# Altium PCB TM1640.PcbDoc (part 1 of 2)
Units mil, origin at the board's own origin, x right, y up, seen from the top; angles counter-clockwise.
Board outline 3858.42 x 1968.54 mil, 2 copper layers (Top Layer, Bottom Layer); 104 components, 33 nets, 245 pads, 113 vias.
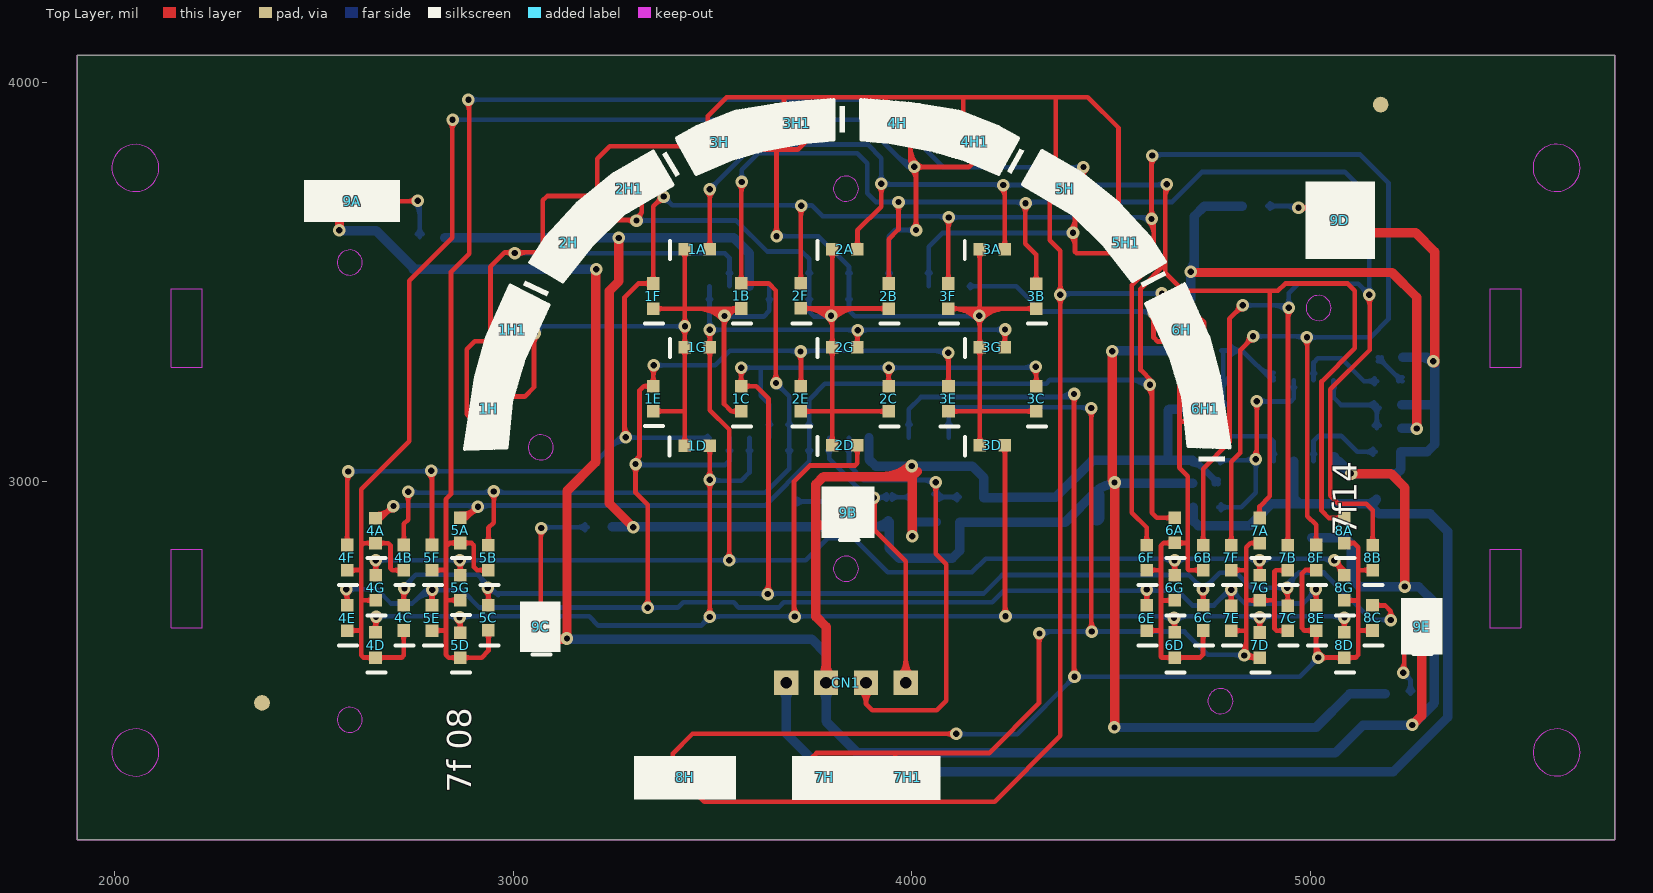
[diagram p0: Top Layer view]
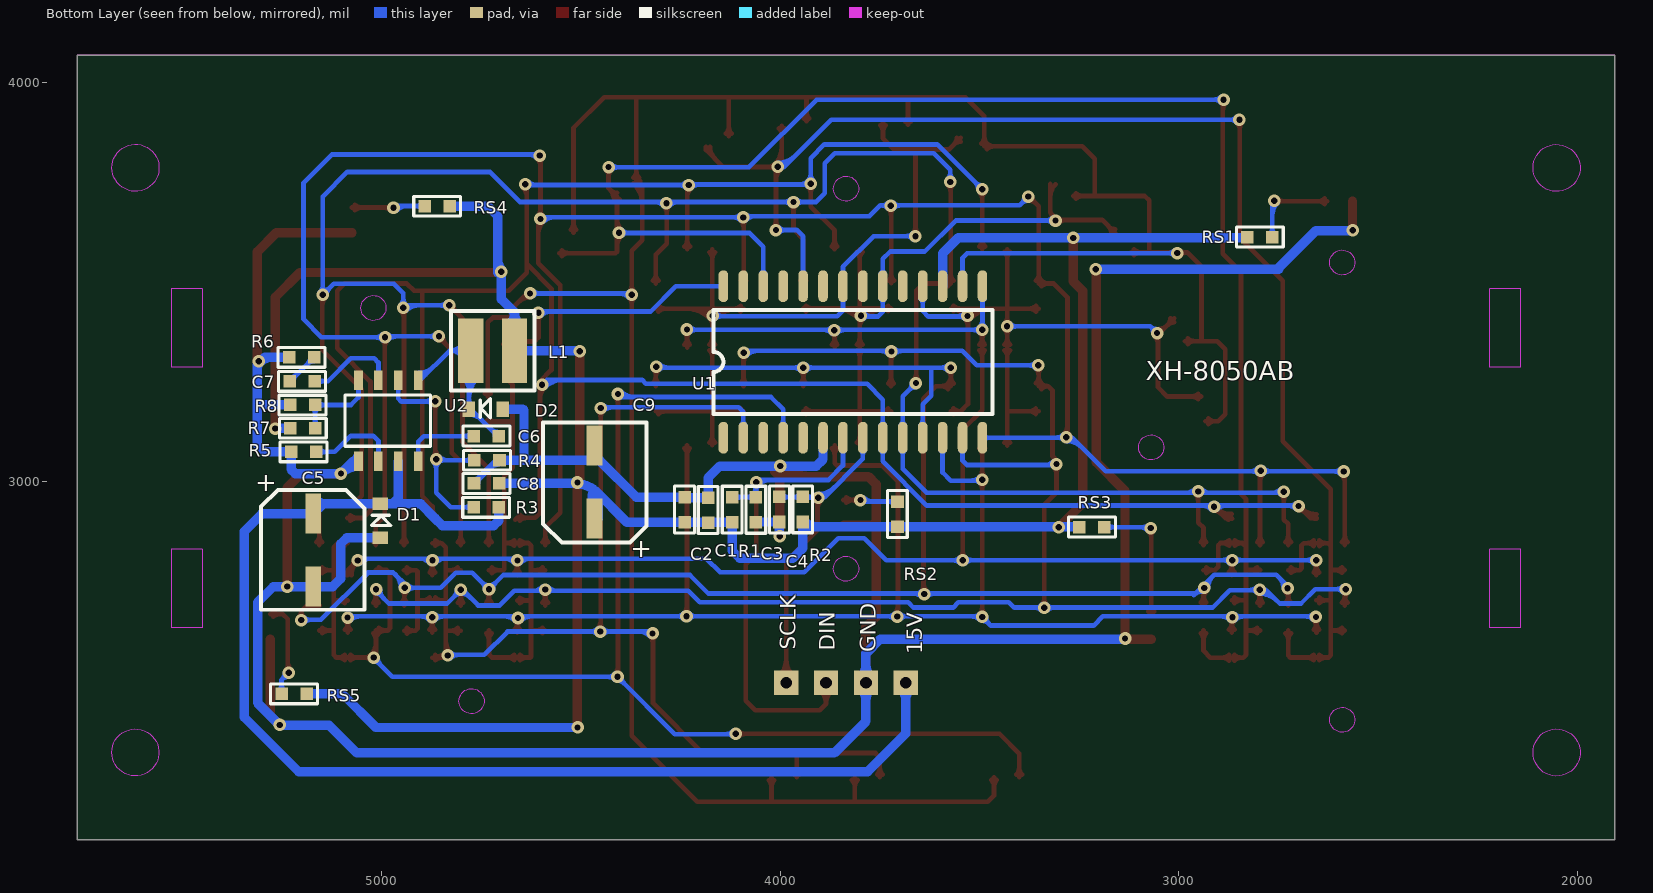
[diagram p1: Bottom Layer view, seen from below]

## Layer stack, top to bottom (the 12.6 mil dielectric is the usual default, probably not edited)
Top Solder: solder mask 0.4, Solder Resist, Dk 3.5
Top Layer: signal copper 1.4
Dielectric 1: dielectric 12.6, FR-4, Dk 4.8
Bottom Layer: signal copper 1.4
Bottom Solder: solder mask 0.4, Solder Resist, Dk 3.5

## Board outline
1905.23,2101.17 5763.65,2101.17 5763.65,4069.72 1905.23,4069.72

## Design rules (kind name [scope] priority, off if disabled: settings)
Clearance [All] p1: gap=10 ignorepadtopadclearanceinfootprint=FALSE
PlaneClearance [All] p1: clearance=0
PolygonConnect [All] p1: connectstyle=Relief reliefconductorwidth=10 reliefentries=4 polygonreliefangle="90 Angle" airgapwidth=10
RoutingPriority [All] p1: routingpriority=4
RoutingVias [All] p1: holewidth=20 width=50 viastyle="Through Hole" minholewidth=28 minwidth=50 maxholewidth=28 maxwidth=50
SolderMaskExpansion [All] p1: expansion=4
Width [All] p1: maxlimit=39.37 minlimit=39.37 preferedwidth=10
28 further rules are at their usual default settings.

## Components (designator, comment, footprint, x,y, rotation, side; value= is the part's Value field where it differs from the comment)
1A "Diode" 0603 3461.42,3582.44 r0 top
1B "Diode" 0603 3571.69,3465.28 r90 top
1C "Diode" 0603 3571.46,3207.4 r90 top
1D "Diode" 0603 3461.26,3090 r0 top
1E "Diode" 0603 3351.06,3207.52 r90 top
1F "Diode" 0603 3350.91,3465 r90 top
1G "Diode" 0603 3461.46,3336.22 r0 top
1H "Diode" 0603 2938.11,3181.93 r260 top
1H1 "Diode" 0603 2997.36,3380.47 r245 top
2A "Diode" 0603 3831.65,3582.44 r0 top
2B "Diode" 0603 3941.81,3465 r90 top
2C "Diode" 0603 3941.53,3207.28 r90 top
2D "Diode" 0603 3831.5,3090.43 r0 top
2E "Diode" 0603 3721.42,3207.24 r90 top
2F "Diode" 0603 3721.14,3465.39 r90 top
2G "Diode" 0603 3831.5,3336.22 r0 top
2H "Diode" 0603 3138.94,3598.9 r230 top
2H1 "Diode" 0603 3290.2,3734.13 r215 top
3A "Diode" 0603 4201.42,3582.2 r0 top
3B "Diode" 0603 4311.73,3464.96 r90 top
3C "Diode" 0603 4311.85,3207.4 r90 top
3D "Diode" 0603 4201.61,3090.28 r0 top
3E "Diode" 0603 4091.53,3207.24 r90 top
3F "Diode" 0603 4091.3,3465 r90 top
3G "Diode" 0603 4201.57,3336.22 r0 top
3H "Diode" 0603 3517.09,3851.53 r200 top
3H1 "Diode" 0603 3710.32,3898.07 r185 top
4A "Diode" 0603 2654.05,2876.61 r90 top
4B "Diode" 0603 2725.04,2808.98 r90 top
4C "Diode" 0603 2724.68,2657.4 r90 top
4D "Diode" 0603 2654.05,2589.53 r90 top
4E "Diode" 0603 2582.95,2657.32 r90 top
4F "Diode" 0603 2583.03,2809.01 r90 top
4G "Diode" 0603 2654.29,2733.11 r90 top
4H "Diode" 0603 3964.72,3898.07 r170 top
4H1 "Diode" 0603 4156.89,3852.44 r155 top
5A "Diode" 0603 2866.3,2876.93 r90 top
5B "Diode" 0603 2937.44,2808.78 r90 top
5C "Diode" 0603 2937.44,2657.56 r90 top
5D "Diode" 0603 2866.77,2589.33 r90 top
5E "Diode" 0603 2795.71,2657.32 r90 top
5F "Diode" 0603 2795.83,2809.01 r90 top
5G "Diode" 0603 2866.46,2733.5 r90 top
5H "Diode" 0603 4384.69,3734.49 r140 top
5H1 "Diode" 0603 4536.14,3598.39 r125 top
6A "Diode" 0603 4659.65,2877.13 r90 top
6B "Diode" 0603 4730.43,2808.74 r90 top
6C "Diode" 0603 4730.35,2657.4 r90 top
6D "Diode" 0603 4659.45,2589.53 r90 top
6E "Diode" 0603 4588.74,2657.32 r90 top
6F "Diode" 0603 4588.66,2808.7 r90 top
6G "Diode" 0603 4659.57,2732.91 r90 top
6H "Diode" 0603 4676.81,3380.47 r110 top
6H1 "Diode" 0603 4735.71,3181.93 r95 top
7A "Diode" 0603 4872.01,2876.73 r90 top
7B "Diode" 0603 4943.11,2808.66 r90 top
7C "Diode" 0603 4942.8,2657.09 r90 top
7D "Diode" 0603 4872.24,2589.45 r90 top
7E "Diode" 0603 4801.34,2657.13 r90 top
7F "Diode" 0603 4801.34,2808.82 r90 top
7G "Diode" 0603 4872.13,2733.11 r90 top
7H "Diode" 0603 3780.91,2257.6 r0 top
7H1 "Diode" 0603 3989.76,2257.52 r0 top
8A "Diode" 0603 5084.96,2876.73 r90 top
8B "Diode" 0603 5155.71,2808.78 r90 top
8C "Diode" 0603 5155.39,2657.4 r90 top
8D "Diode" 0603 5084.69,2589.53 r90 top
8E "Diode" 0603 5013.78,2657.32 r90 top
8F "Diode" 0603 5013.9,2809.01 r90 top
8G "Diode" 0603 5084.69,2732.91 r90 top
8H "Diode" 0603 3431.46,2257.6 r0 top
9A "Diode" 0603 2595.2,3702.91 r0 top
9B "Diode" 0603 3840.59,2921.73 r90 top
9C "Diode" 0603 3068.58,2635.24 r90 top
9D "Diode" 0603 5073.74,3655.63 r90 top
9E "Diode" 0603 5278.46,2635.67 r90 top
C1 "Cap" 电阻正面 4179.92,2927.76 r270 bottom
C2 "Cap" 电阻正面 4239.21,2929.21 r270 bottom
C3 "Cap" 电阻正面 4060.94,2929.21 r90 bottom
C4 "Cap" 电阻正面 4001.65,2929.68 r90 bottom
C5 "Cap Pol2" 电解电容47UF 5171.02,2918.94 r180 bottom
C6 "Cap" 电阻正面 4736.93,3113.62 r0 bottom
C7 "Cap" 电阻正面 5198.9,3251.5 r180 bottom
C8 "Cap" 电阻正面 4736.26,2994.96 r180 bottom
C9 "Cap Pol2" 电解电容47UF 4465.55,2906.5 r0 bottom
CN1 "Header 4" 0.75(1-4) 3684.44,2494.68 r0 top
D1 "TVS" SOD-323 5002.8,2858.86 r90 top
D2 "TVS" SOD-323 4696.06,3181.38 r0 top
L1 "Inductor" 电感404018 4775.98,3328.23 r90 bottom
R1 "Res2" 电阻正面 4119.72,2928.74 r270 bottom
R2 "Res2" 电阻正面 3942.87,2929.68 r270 bottom
R3 "Res2" 电阻正面 4736.73,2935.24 r180 bottom
R4 "Res2" 电阻正面 4735.24,3052.76 r0 bottom
R5 "Res2" 电阻正面 5195.04,3074.29 r180 bottom
R6 "Res2" 电阻正面 5200.2,3311.57 r180 bottom
R7 "Res2" 电阻正面 5197.6,3133.07 r0 bottom
R8 "Res2" 电阻正面 5197.6,3191.85 r180 bottom
RS1 "Res2" 电阻正面 2796.5,3612.99 r0 bottom
RS2 "Res2" 电阻正面 3705.24,2917.91 r270 bottom
RS3 "Res2" 电阻正面 3217.83,2885.28 r0 bottom
RS4 "Res2" 电阻正面 4859.76,3690.79 r180 bottom
RS5 "Res2" 电阻正面 5219.06,2467.4 r180 bottom
U1 "Component_1" sop28 4142.13,3109.68 r90 bottom locked
U2 "MP1584" SOP8 4907.52,3253.66 r0 top locked

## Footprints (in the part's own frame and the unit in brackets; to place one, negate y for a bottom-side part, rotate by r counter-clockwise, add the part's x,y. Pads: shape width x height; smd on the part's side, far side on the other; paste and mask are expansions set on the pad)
0.75(1-4) [mm]
  rect 1.54x1.54 hole 0.75: 1(0,0) 2(2.54,0) 3(5.08,0) 4(7.62,0)
0603 [mm]
  rect 0.8x0.8 smd: 1(0.8,0) 2(-0.8,0)
  silkscreen extent -1.75,-0.63 -1.75,0.52
SOD-323 [mm]
  rect 0.8x1 smd far side: 1(0,0) 2(2.15,0)
SOP8 [mm]
  rect 0.55x1.25 smd far side: 1(0,0) 2(1.27,0) 3(2.54,0) 4(3.81,0) 5(3.81,-5.15) 6(2.54,-5.15) 7(1.27,-5.15) 8(0,-5.15)
  round 0.8 on Bottom Overlay: 9(-0.038,-1.664)
sop28 [mil]
  oval 80x24 smd: 1(0,0) 2(0,-50) 3(0,-100) 4(0,-150) 5(0,-200) 6(0,-250) 7(0,-300) 8(0,-350) 9(0,-400) 10(0,-450) 11(0,-500) 12(0,-550) 13(0,-600) 14(0,-650) 15(380,-650) 16(380,-600) 17(380,-550) 18(380,-500) 19(380,-450) 20(380,-400) 21(380,-350) 22(380,-300) 23(380,-250) 24(380,-200) 25(380,-150) 26(380,-100) 27(380,-50) 28(380,0)
  silkscreen extent 60,-675 320,25
电感404018 [mm]
  rect 4.1x1.6 smd: 1(0,0) 2(0,-2.8)
  silkscreen extent -2.55,-4.08 2.53,1.26
电解电容47UF [mm]
  rect 1x2.55 smd: 1(0,0) 2(0,-4.65)
  silkscreen extent -3.32,-6.12 3.27,1.52
电阻正面 [mm]
  rect 0.8x0.8 smd: 1(-0.8,0) 2(0.8,0)
  silkscreen extent -1.5,-0.64 1.49,0.62

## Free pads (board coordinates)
  round 39.37 smd: 1(2369.25,2444.29) 2(5175.79,3945.47)

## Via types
v1: diameter 31.5, hole 15.75, Top Layer to Bottom Layer, 113 vias

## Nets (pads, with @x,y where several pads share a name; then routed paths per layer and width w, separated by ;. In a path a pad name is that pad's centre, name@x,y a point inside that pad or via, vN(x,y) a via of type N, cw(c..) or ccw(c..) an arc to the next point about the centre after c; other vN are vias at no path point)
5V: C1.2 C2.2 C8.2 C9.1 L1.2 R1.2 R2.2 R7.2 RS1.2 RS2.2 RS3.2 RS4.2 RS5.2 U1.17 | length 6721.8
  Top Layer w23.62: v1(3264.61,3610.91) 3264.61,3501.97 3240.39,3477.76 3240.39,2945.43 v1(3300.71,2885.12) ; v1@4502.2,3002.76 v1(4502.2,3326.85) ; v1@4508.23,2384.17 v1(4508.23,2997.24) ; v1@4700.43,3524.17 5204.25,3524.17 5266.42,3462.01 v1(5266.42,3132.56)
  Bottom Layer w23.62: RS1.2@2827.48,3610.91 v1(3264.61,3610.91) 3553.19,3610.91 3592.13,3571.97 U1.17@3592.13,3489.68 ; RS3.2@3248.15,2886.42 RS2.2@3705.24,2886.42 R2.2@3938.11,2886.42 ; 3904.95,2886.42 ccw(c3904.95,2936.11) R2.2@3940.09,2900.97 ; R2.2@3942.87,2898.19 3942.87,2831.89 3967.64,2807.13 4100.98,2807.13 4119.72,2825.87 R1.2@4119.72,2897.24 4383.86,2897.24 4463.58,2976.97 ; 4463.58,2976.71 cw(c4508.23,2924.97) v1@4508.23,2993.31 ; v1@4505.12,3328.23 L1.2@4665.75,3328.23 4665.75,3423.98 4699.13,3457.36 v1(4699.13,3525.98) ; v1(4507.87,2382.72) 5013.82,2382.72 5098.5,2467.4 RS5.2@5187.56,2467.4 ; v1@4508.23,2994.96 C8.2@4704.76,2994.96 ; L1.2@4652.04,3391.57 ccw(c4620.59,3423.97) 4665.75,3423.97 ccw(c4710.9,3423.97) L1.2@4679.46,3391.57 ; v1@4696.35,3528.77 ccw(c4668.34,3556.78) 4707.95,3556.78 ; v1@4707.95,3523.58 4707.95,3665.16 4733.58,3690.79 RS4.2@4828.27,3690.79 ; R7.2@5229.09,3133.07 v1@5266.06,3133.07
  Bottom Layer w39.37: C9.1@4463.58,2908.46 4463.58,2964.57
15V: C5.1 CN1.1 D1.2 R3.2 U2.7 | length 3313.9
  Bottom Layer w23.62: CN1.1@3671.35,2481.59 cw(c3639.77,2450.01) 3684.44,2450.01 cw(c3729.11,2450.01) CN1.1@3697.52,2481.59 ; CN1.1@3684.44,2494.68 3684.44,2367.65 3780.28,2271.81 5207.64,2271.81 5344.37,2408.54 5344.37,2874.41 5299.84,2918.94 C5.1@5171.02,2918.94 5146.46,2943.5 ; R3.2@4705.24,2935.24 4705.24,2902.01 4717.99,2889.25 4847.28,2889.25 4865.35,2907.32 4901.53,2943.5 4972.48,2943.5 ; U2.7@4957.52,3050.91 4957.52,2958.46 4972.48,2943.5 ; 5137.66,2943.5 ccw(c5137.66,2982.81) C5.1@5165.46,2955.02 ; C5.1@5164.29,2953.54 cw(c5146.46,2964.38) 5146.46,2943.5 ; 4972.48,2943.5 D1.2@5002.8,2943.5 5146.46,2943.5
DIN: C3.2 CN1.3 R1.1 U1.7 | length 1545.6
  Top Layer w11.81: CN1.3@3868.75,2475.98 cw(c3840.52,2442.33) 3884.44,2442.33 ; CN1.3@3884.44,2494.68 3884.44,2442.33 ; CN1.3@3900.13,2475.98 ccw(c3928.36,2442.33) 3884.44,2442.33 ; v1@4052.57,2991.27 cw(c4035.76,2974.47) 4059.53,2974.47 cw(c4083.29,2974.47) v1@4066.49,2991.27 ; v1(4059.53,2998.23) 4059.53,2818.78 4086.26,2792.05 4086.26,2449.84 4062.36,2425.94 3900.83,2425.94 3884.44,2442.33
  Bottom Layer w11.81: U1.7@3837.82,3077.37 cw(c3827.41,3066.97) 3842.12,3066.97 ; 3842.13,3066.97 cw(c3856.84,3066.97) U1.7@3846.44,3077.37 ; U1.7@3842.13,3109.68 3842.13,3040 3878.35,3003.78 4026.99,3003.78 ; v1@4051.92,2991.99 ccw(c4027,2971.55) 4027,3003.78 ; v1@4052.57,2991.27 cw(c4032.34,2971.04) C3.2@4060.94,2971.04 ; C3.2@4053.98,2967.67 ccw(c4037.18,2984.47) 4060.94,2984.47 ccw(c4084.71,2984.47) 4067.9,2967.67 ccw(c4084.71,2984.47) 4084.71,2960.71 ccw(c4084.71,2936.95) C3.2@4067.9,2953.75 ; 4060.95,2977.89 cw(c4079.87,2977.89) v1@4066.49,2991.27 ; 4094.82,2960.71 cw(c4094.82,2935.33) R1.1@4112.76,2953.28 ; 4097.1,2960.71 ccw(c4097.1,2982.86) R1.1@4112.76,2967.2 ; R1.1@4119.25,2960.71 C3.2@4060.94,2960.71 4060.94,2996.1 4053.27,3003.78 4026.99,3003.78
GND: 9A.2 9B.2 9C.2 9D.2 9E.2 C1.1 C2.1 C3.1 C4.1 C5.2 C8.1 C9.2 CN1.2 D1.1 D2.1 R4.1 R5.1 R6.1 R8.1 U1.6 U2.5 | length 9586.3
  Top Layer w23.62: v1@2563.7,3630.98 9A.2@2563.7,3702.91 ; 9C.2@3068.58,2603.74 v1@3132.16,2603.74 ; v1(3134.37,2605.94) 3134.37,2976.1 3206.77,3048.5 v1@3206.77,3532.32 ; CN1.2@3771.35,2507.76 ccw(c3739.77,2539.35) 3784.44,2539.35 ccw(c3829.11,2539.35) CN1.2@3797.52,2507.76 ; CN1.2@3784.44,2494.68 3784.44,2635.24 3758.94,2660.75 3758.94,2898.23 ; 9B.2@3840.59,2890.24 3766.93,2890.24 3758.94,2898.23 ; 3925.51,3011.97 ccw(c3925.51,3112.88) v1@3996.86,3041.52 ; 3982.54,3011.97 ccw(c3982.54,3055.85) 4013.56,3024.82 ; 3999.13,3011.97 3778.11,3011.97 3758.94,2992.8 3758.94,2898.23 ; v1(4000.35,2862.76) v1@4000.35,3032.44 ; 9D.2@5073.74,3624.13 5263.27,3624.13 5311.65,3575.75 v1@5311.65,3297.4 ; v1@5106.22,3019.49 5201.57,3019.49 5236.46,2984.61 v1(5236.46,2736.26) ; v1(5255.35,2388.98) 5278.46,2412.09 9E.2@5278.46,2604.17 ; v1@5305.13,3304.08 ccw(c5289.38,3319.83) 5311.65,3319.83
  Bottom Layer w15.75: R4.1@4703.74,3044.88 cw(c4703.74,3010.86) 4727.8,3034.92 ; R4.1@4709.96,3052.76 C8.1@4767.76,2994.96 ; C8.1@4759.88,2994.96 ccw(c4740.88,2994.96) 4754.31,3008.4 ccw(c4767.76,3021.85) C8.1@4767.76,3002.83
  Bottom Layer w23.62: v1@2563.7,3629.17 2655.2,3629.17 2747.95,3536.42 ; 2748.39,3532.64 v1@3208.74,3532.64 ; v1@3136.26,2604.49 3748.43,2604.49 3784.44,2568.47 CN1.2@3784.44,2494.68 3784.44,2397.88 3863.54,2318.78 5061.81,2318.78 5131.42,2388.39 v1@5254.49,2388.39 ; CN1.2@3771.35,2481.59 cw(c3739.77,2450.01) 3784.44,2450.01 cw(c3829.11,2450.01) CN1.2@3797.52,2481.59 ; CN1.2@3771.35,2507.76 ccw(c3739.77,2539.35) 3784.44,2539.35 ccw(c3829.11,2539.35) CN1.2@3797.52,2507.76 ; U1.6@3892.13,3109.68 3892.13,3055.16 3909.33,3037.95 4151.46,3037.95 4179.92,3009.49 C1.1@4179.92,2959.25 C2.1@4237.76,2959.25 ; v1@4001.65,2862.76 C4.1@4001.65,2898.19 C3.1@4060.47,2898.19 ; C2.1@4239.21,2960.71 4360.51,2960.71 4452.56,3052.76 4649.69,3052.76 ; D2.1@4696.06,3181.38 4645.16,3181.38 4642.2,3178.43 4642.2,3060.24 4649.69,3052.76 ; R4.1@4703.74,3052.76 4649.69,3052.76 ; D1.1@5002.8,2858.86 5086.53,2858.86 5101.97,2843.43 5101.97,2756.26 5122.36,2735.87 C5.2@5171.02,2735.87 5271.53,2735.87 5310.75,2696.65 5310.75,2444.37 v1(5255.35,2388.98) ; U2.5@5057.52,3038.11 cw(c5057.52,2976.33) v1@5101.2,3020.01 ; U2.5@5057.52,3050.91 5070.31,3050.91 v1(5101.5,3019.72) 5216.1,3019.72 5226.53,3030.16 R5.1@5226.53,3074.29 5292.6,3074.29 5311.65,3093.35 5311.65,3293.11 5293.19,3311.57 R6.1@5231.69,3311.57 ; U2.5@5057.52,3061.73 cw(c5057.52,3056.98) U2.5@5060.88,3060.34 ; R8.1@5229.09,3191.85 5307.16,3191.85 ; 5273.6,3311.57 cw(c5273.6,3266.99) 5305.13,3298.51 cw(c5289.38,3282.76) 5311.65,3282.76
  other v1: 3999.64,3038.74 5307.91,3301.3 3208.15,3532.32 2563.03,3630.31
GRID1: 1A.2 1B.2 1C.2 1D.2 1E.2 1F.2 1G.2 1H1.2 1H.2 U1.18 | length 2898.4
  Top Layer w11.81: 1H.2@2943.58,3212.95 3028.54,3212.95 3051.69,3236.1 3051.69,3368 1H1.2@3010.67,3409.02 ; 1H.2@2950.54,3205.99 cw(c2967.34,3189.18) 2967.34,3212.95 cw(c2967.34,3236.71) 1H.2@2950.54,3219.91 ; 1H1.2@3010.67,3399.17 cw(c3010.67,3375.41) 3027.47,3392.21 ; 1H1.2@3020.52,3409.02 ccw(c3044.28,3409.02) 3027.48,3392.22 ; 3026.2,3393.49 ccw(c3054.01,3421.3) v1@3054.01,3381.97 ; v1@3047.06,3365.17 cw(c3035.86,3353.97) 3051.69,3353.97 ; 3051.69,3342.76 cw(c3083.39,3342.76) v1@3060.98,3365.17 ; 1F.2@3350.91,3433.5 3429.92,3433.5 ; 1E.2@3351.06,3176.02 3427.52,3176.02 ; 1F.2@3357.87,3426.54 cw(c3374.67,3409.74) 3374.67,3433.5 cw(c3374.67,3457.26) 1F.2@3357.87,3440.46 ; 1E.2@3358.02,3169.06 cw(c3374.82,3152.26) 3374.82,3176.02 cw(c3374.82,3199.78) 1E.2@3358.02,3182.98 ; 1D.2@3422.8,3096.96 ccw(c3405.62,3114.14) 3429.92,3114.14 ; 1A.2@3422.96,3575.48 cw(c3406.16,3558.68) 3429.92,3558.68 cw(c3453.68,3558.68) 1A.2@3436.88,3575.48 ; 1G.2@3423,3329.26 cw(c3406.29,3312.55) 3429.92,3312.55 ; 1G.2@3423,3343.18 ccw(c3406.29,3359.89) 3429.92,3359.89 ; v1@3423.28,3382.06 cw(c3407.23,3366.01) 3429.92,3366.01 ; v1@3423.28,3395.98 ccw(c3407.23,3412.02) 3429.92,3412.02 ; 1D.2@3429.92,3090.16 3429.92,3389.01 3429.92,3433.5 ; 3429.92,3113.38 ccw(c3453.14,3113.38) 1D.2@3436.72,3096.96 ; 3429.92,3312.36 cw(c3453.82,3312.36) 1G.2@3436.92,3329.26 ; 3429.92,3360.08 ccw(c3453.82,3360.08) 1G.2@3436.92,3343.18 ; 3429.92,3364.49 cw(c3454.76,3364.49) v1@3437.2,3382.06 ; 3429.92,3413.54 ccw(c3454.76,3413.54) v1@3437.2,3395.98 ; 1A.2@3429.92,3582.44 3429.92,3433.5 ; 3461.5,3433.5 cw(c3461.5,3346.97) 3522.69,3408.16 cw(c3508.73,3394.2) 3528.47,3394.2 ; 3490.01,3433.5 cw(c3490.01,3375.48) v1@3531.04,3416.51 ; v1@3516.86,3420.26 cw(c3536.46,3412.38) 3536.46,3433.5 ; 3518.52,3433.5 cw(c3518.52,3404) v1@3539.39,3424.86 ; v1@3523.38,3422.71 ccw(c3514.47,3433.5) 3528.47,3433.5 ; v1@3527.82,3415.85 cw(c3553.94,3405.35) 3553.94,3433.5 ; 3528.47,3388.51 cw(c3556.25,3388.51) v1@3536.61,3408.16 ; v1@3534.28,3423.8 cw(c3539.47,3433.5) 3528.47,3433.5 ; v1@3538.78,3411.45 cw(c3571.41,3398.33) 3571.41,3433.5 3528.47,3433.5 ; 3547.26,3433.5 ccw(c3547.26,3458.21) 1B.2@3564.73,3440.74 ; 3548.6,3433.5 cw(c3548.6,3410.68) 1B.2@3564.73,3426.82 ; 1C.2@3564.5,3168.94 ccw(c3547.69,3152.14) 3547.69,3175.9 ccw(c3547.69,3199.67) 1C.2@3564.5,3182.87 ; 1C.2@3571.46,3175.91 3546.77,3175.91 3528.47,3194.21 3528.47,3433.5 ; 3429.92,3433.5 3528.47,3433.5
  Bottom Layer w11.81: v1(3054.01,3372.13) 3070.91,3389.01 v1(3430.24,3389.01) ; v1@3054.01,3381.97 ccw(c3054.01,3405.73) 3070.82,3388.93 ccw(c3087.62,3372.13) v1@3063.86,3372.13 ; v1@3423.28,3382.05 ccw(c3406.47,3365.25) 3406.47,3389.01 ccw(c3406.47,3412.78) v1@3423.28,3395.98 ; v1@3531.18,3413.5 3627.64,3413.5 3642.13,3427.99 U1.18@3642.13,3489.68 ; v1@3536.61,3408.16 cw(c3549.51,3395.25) 3549.51,3413.5 ; v1@3536.6,3422.08 ccw(c3557.3,3442.78) 3557.3,3413.5 ; U1.18@3637.82,3457.37 cw(c3627.41,3446.97) 3642.12,3446.97 ; 3642.13,3446.97 cw(c3656.84,3446.97) U1.18@3646.44,3457.37
  other v1: 3529.64,3415.12
GRID2: 2A.2 2B.2 2C.2 2D.2 2E.2 2F.2 2G.2 2H1.2 2H.2 U1.20 | length 2788.4
  Top Layer w11.81: 2H.2@3159.18,3623.02 3192.06,3655.91 3303.39,3655.91 3322.05,3674.57 ; 2H.2@3159.18,3632.87 ccw(c3159.18,3656.63) 3175.98,3639.83 ccw(c3192.79,3623.02) 2H.2@3169.03,3623.02 ; 3281.67,3655.9 cw(c3281.67,3627.3) v1@3301.9,3647.53 ; 3288.52,3655.91 ccw(c3288.52,3674.83) v1@3301.9,3661.45 ; 2H1.2@3309.04,3745.24 cw(c3277.63,3713.83) 3322.05,3713.83 ; v1@3318.16,3657.7 cw(c3333.58,3663.03) 3322.05,3674.57 ; 2H1.2@3322.05,3746.15 3322.05,3674.57 ; 2F.2@3721.14,3433.9 3800.16,3433.9 ; 2E.2@3721.42,3175.75 3800.16,3175.75 ; 2F.2@3728.1,3426.94 cw(c3744.9,3410.14) 3744.9,3433.9 cw(c3744.9,3457.66) 2F.2@3728.1,3440.86 ; 2E.2@3728.38,3168.79 cw(c3745.18,3151.99) 3745.18,3175.75 cw(c3745.18,3199.51) 2E.2@3728.38,3182.71 ; 2F.2@3729.89,3433.9 cw(c3729.89,3348.71) 3790.13,3408.95 cw(c3765.91,3384.73) 3800.16,3384.73 ; 3758.4,3433.9 cw(c3758.4,3377.22) v1@3798.48,3417.3 ; 3786.92,3433.9 cw(c3786.92,3405.74) v1@3806.83,3425.65 ; v1@3787.34,3425.65 cw(c3807.26,3405.74) 3807.26,3433.9 ; v1@3790.13,3422.87 ccw(c3765.91,3447.08) 3800.16,3447.08 ; 2D.2@3793.04,3097.39 ccw(c3775.86,3114.57) 3800.16,3114.57 ; 2G.2@3793.04,3329.26 cw(c3775.86,3312.08) 3800.16,3312.08 ; 2G.2@3793.04,3343.18 ccw(c3775.86,3360.36) 3800.16,3360.36 ; 2A.2@3793.2,3575.48 cw(c3776.39,3558.68) 3800.16,3558.68 cw(c3823.92,3558.68) 2A.2@3807.12,3575.48 ; v1@3795.7,3417.3 cw(c3835.77,3377.22) 3835.77,3433.9 ; 2D.2@3800.16,3090.59 3800.16,3175.75 ; 3800.16,3113.82 ccw(c3823.38,3113.82) 2D.2@3806.96,3097.39 ; 3800.16,3312.84 cw(c3823.38,3312.84) 2G.2@3806.96,3329.26 ; 3800.16,3359.6 ccw(c3823.38,3359.6) 2G.2@3806.96,3343.18 ; 3800.16,3399.56 cw(c3813.43,3399.56) 3804.05,3408.95 cw(c3864.28,3348.71) 3864.28,3433.9 ; 2A.2@3800.16,3582.44 3800.16,3433.9 ; 3917.1,3433.9 cw(c3917.1,3408.79) 2B.2@3934.85,3426.54 ; 3917.68,3175.75 ccw(c3917.68,3199.64) 2C.2@3934.58,3182.75 ; 3917.87,3175.75 cw(c3917.87,3152.12) 2C.2@3934.57,3168.83 ; 3919,3433.9 ccw(c3919,3456.32) 2B.2@3934.85,3440.46 ; 2B.2@3941.42,3433.9 3800.16,3433.9 ; 2C.2@3941.49,3175.75 3800.16,3175.75 ; 3800.16,3175.75 3800.16,3433.9 ; 3800.16,3432.25 ccw(c3813.43,3432.25) v1@3804.05,3422.86 ; 3800.16,3432.25 ccw(c3813.43,3432.25) v1@3804.05,3422.86 ; 3800.16,3432.25 ccw(c3813.43,3432.25) v1@3804.05,3422.86 ; 3800.16,3433.9 cw(c3791.01,3433.9) 3793.94,3425.23 ccw(c3791.01,3433.9) 3800.16,3433.9
  Bottom Layer w11.81: v1(3308.86,3654.49) 3559.13,3654.49 3636.77,3576.85 3723.7,3576.85 3742.13,3558.43 U1.20@3742.13,3489.68 3742.13,3425.28 3753.54,3413.86 v1@3798.98,3413.86 ; v1@3315.82,3647.53 cw(c3332.62,3630.73) 3332.62,3654.49 cw(c3332.62,3678.25) v1@3315.82,3661.45 ; U1.20@3737.82,3457.37 cw(c3727.41,3446.97) 3742.12,3446.97 ; U1.20@3737.82,3521.99 ccw(c3727.41,3532.4) 3742.12,3532.4 ; 3742.13,3446.97 cw(c3756.84,3446.97) U1.20@3746.44,3457.37 ; 3742.13,3532.4 ccw(c3756.84,3532.4) U1.20@3746.44,3521.99 ; 3768.38,3413.86 ccw(c3768.38,3444.61) v1@3790.13,3422.86 ; 3778.27,3413.86 cw(c3778.27,3397.09) v1@3790.13,3408.95
  other v1: 3797.09,3415.91
GRID3: 3A.2 3B.2 3C.2 3D.2 3E.2 3F.2 3G.2 3H1.2 3H.2 U1.22 | length 2974.7
  Top Layer w11.81: 3H.2@3546.68,3852.46 cw(c3546.68,3828.7) 3563.48,3845.5 cw(c3580.29,3862.31) 3H.2@3556.53,3862.31 ; 3H.2@3546.68,3862.31 3576.31,3832.68 3660.02,3832.68 ; v1@3653.32,3622.23 ccw(c3637.12,3638.43) 3660.02,3638.43 ; v1@3660.02,3620.97 3660.02,3832.68 ; 3660.02,3639.65 ccw(c3684.65,3639.65) v1@3667.24,3622.24 ; 3H1.2@3734.73,3893.86 cw(c3717.93,3877.05) 3741.69,3877.05 cw(c3765.45,3877.05) 3H1.2@3748.65,3893.86 ; 3H1.2@3741.69,3900.82 3741.69,3861.06 3713.31,3832.68 3660.02,3832.68 ; 3F.2@4091.3,3433.5 4169.92,3433.5 ; 3E.2@4091.53,3175.75 4169.92,3175.75 ; 3F.2@4098.26,3426.54 cw(c4115.06,3409.74) 4115.06,3433.5 cw(c4115.06,3457.26) 3F.2@4098.26,3440.46 ; 3E.2@4098.5,3168.79 cw(c4115.3,3151.99) 4115.3,3175.75 cw(c4115.3,3199.51) 3E.2@4098.5,3182.71 ; 3F.2@4102.17,3433.5 cw(c4102.17,3348.98) 4161.94,3408.75 cw(c4142.66,3389.47) 4169.92,3389.47 ; 4130.69,3433.5 cw(c4130.69,3377.5) v1@4170.29,3417.1 ; v1@4159.15,3425.45 cw(c4178.59,3406.01) 4178.59,3433.5 ; 4159.2,3433.5 cw(c4159.2,3406.01) v1@4178.64,3425.45 ; v1@4161.94,3422.67 ccw(c4142.66,3441.94) 4169.92,3441.94 ; 3A.2@4162.96,3575.24 cw(c4146.16,3558.44) 4169.92,3558.44 cw(c4193.68,3558.44) 3A.2@4176.88,3575.24 ; 3G.2@4163.12,3329.26 cw(c4146.7,3312.84) 4169.92,3312.84 ; 3G.2@4163.12,3343.18 ccw(c4146.7,3359.6) 4169.92,3359.6 ; 3D.2@4163.16,3097.24 ccw(c4146.83,3113.56) 4169.92,3113.56 ; v1@4167.51,3417.1 cw(c4207.11,3377.5) 4207.11,3433.5 ; 3D.2@4169.92,3090.47 4169.92,3175.75 ; 4169.92,3114.51 ccw(c4194.35,3114.51) 3D.2@4177.08,3097.24 ; 4169.92,3312.08 cw(c4194.22,3312.08) 3G.2@4177.04,3329.26 ; 4169.92,3360.36 ccw(c4194.22,3360.36) 3G.2@4177.04,3343.18 ; 4169.92,3394.42 cw(c4190.19,3394.42) 4175.86,3408.75 cw(c4235.62,3348.98) 4235.62,3433.5 ; 4169.92,3437 ccw(c4190.19,3437) v1@4175.86,3422.67 ; 3A.2@4169.92,3582.2 4169.92,3433.5 ; 4287.71,3175.75 ccw(c4287.71,3200.05) 3C.2@4304.89,3182.87 ; 4287.88,3433.5 cw(c4287.88,3409.61) 3B.2@4304.77,3426.5 ; 4288.06,3433.5 ccw(c4288.06,3457.13) 3B.2@4304.77,3440.42 ; 4288.47,3175.75 cw(c4288.47,3152.52) 3C.2@4304.89,3168.94 ; 3C.2@4311.69,3175.75 4169.92,3175.75 ; 3B.2@4311.73,3433.46 4169.92,3433.5 ; 4169.92,3175.75 4169.92,3433.5 ; 4169.92,3433.5 cw(c4159.76,3433.5) 4164.4,3424.46 ccw(c4159.76,3433.5) 4169.92,3433.5 ; 4169.92,3433.5 ccw(c4182.44,3433.5) 4174.86,3423.54 cw(c4182.44,3433.5) 4169.92,3433.5
  Bottom Layer w11.81: v1(3660.28,3615.28) 3765.2,3615.28 3842.13,3538.35 U1.22@3842.13,3489.68 3842.13,3428.46 3856.38,3414.21 v1@4169.21,3414.21 ; v1@3667.24,3608.31 cw(c3684.04,3591.51) 3684.04,3615.27 ; v1@3667.24,3622.24 ccw(c3684.04,3639.04) 3684.04,3615.28 ; U1.22@3837.82,3457.37 cw(c3827.41,3446.97) 3842.12,3446.97 ; U1.22@3837.82,3521.99 ccw(c3827.41,3532.4) 3842.12,3532.4 ; 3842.13,3446.97 cw(c3856.84,3446.97) U1.22@3846.44,3457.37 ; 3842.13,3532.4 ccw(c3856.84,3532.4) U1.22@3846.44,3521.99 ; 4141.52,3414.21 ccw(c4141.52,3443.08) v1@4161.94,3422.67 ; 4148.75,3414.21 cw(c4148.75,3395.56) v1@4161.94,3408.75
  other v1: 4168.9,3415.71
GRID4: 4A.2 4B.2 4C.2 4D.2 4E.2 4F.2 4G.2 4H1.2 4H.2 U1.24 | length 4565.9
  Top Layer w11.81: 4E.2@2582.95,2625.83 2618.35,2625.83 ; 4F.2@2583.03,2777.52 2617.28,2777.52 ; 4E.2@2589.91,2618.87 cw(c2606.71,2602.06) 2606.71,2625.82 ; 4E.2@2589.91,2632.79 ccw(c2606.71,2649.59) 2606.71,2625.83 ; 4F.2@2589.99,2770.56 cw(c2606.79,2753.76) 2606.79,2777.52 cw(c2606.79,2801.28) 4F.2@2589.99,2784.48 ; 2621.65,2701.61 4G.2@2654.29,2701.61 ; 4D.2@2647.09,2551.07 ccw(c2630.29,2534.27) 2630.29,2558.03 ccw(c2630.29,2581.79) 4D.2@2647.09,2564.99 ; 4A.2@2647.09,2838.16 ccw(c2630.29,2821.36) 2630.29,2845.12 ccw(c2630.29,2868.88) 4A.2@2647.09,2852.08 ; 4G.2@2647.33,2694.65 ccw(c2630.53,2677.85) 2630.53,2701.61 ccw(c2630.53,2725.38) 4G.2@2647.33,2708.57 ; 4D.2@2661.01,2551.07 cw(c2677.82,2534.27) 2677.82,2558.03 cw(c2677.82,2581.79) 4D.2@2661.01,2564.99 ; 4A.2@2661.01,2838.16 cw(c2677.82,2821.36) 2677.82,2845.12 cw(c2677.82,2868.88) 4A.2@2661.01,2852.08 ; 4C.2@2717.72,2618.94 cw(c2700.92,2602.14) 2724.68,2602.14 cw(c2748.45,2602.14) 4C.2@2731.64,2618.94 ; 4B.2@2718.08,2770.52 ccw(c2701.28,2753.72) 2701.28,2777.48 ccw(c2701.28,2801.24) 4B.2@2718.08,2784.44 ; 4C.2@2724.68,2625.91 2724.68,2563.39 2719.33,2558.03 4D.2@2654.05,2558.03 2623.98,2558.03 2618.35,2563.66 2618.35,2625.83 ; 4B.2@2725.04,2777.48 2696.22,2777.48 2691.53,2782.16 2691.53,2839.72 2686.14,2845.12 4A.2@2654.05,2845.12 2624.88,2845.12 2618.35,2838.58 ; v1@2840.44,3900.36 cw(c2825.92,3885.84) 2846.45,3885.84 ; 2846.46,3881.28 cw(c2873.44,3881.28) v1@2854.36,3900.36 ; v1@2846.46,3907.99 2846.46,3610.98 2738.46,3502.99 2738.46,3100.83 2618.35,2980.71 2618.35,2838.58 ; 4H.2@3988.78,3885.64 cw(c3971.98,3868.84) 3995.74,3868.84 cw(c4019.5,3868.84) 4H.2@4002.7,3885.64 ; 3995.74,3809.25 ccw(c4025.82,3809.25) v1@4004.55,3787.98 ; 3995.74,3837.76 ccw(c4054.34,3837.76) 4012.9,3796.33 ccw(c4031.13,3814.56) 4031.13,3788.78 ; 4H.2@3995.74,3892.6 3995.74,3803.23 v1@4010.2,3788.78 ; v1@3998.98,3782.41 cw(c3971.92,3755.34) 4010.2,3755.34 ; v1@4003.24,3637.51 ccw(c3986.43,3654.31) 4010.2,3654.31 ccw(c4033.96,3654.31) v1@4017.16,3637.51 ; v1(4010.2,3630.55) v1@4010.2,3788.78 ; v1@4012.9,3782.41 cw(c4028.28,3767.03) 4028.28,3788.78 ; 4163.29,3809.43 ccw(c4133.59,3839.13) 4H1.2@4175.59,3839.13 ; 4H1.2@4185.43,3839.13 4185.43,3831.58 4142.64,3788.78 v1@4010.2,3788.78 ; 2618.35,2625.83 2618.35,2838.58
  Bottom Layer w11.81: v1(2847.4,3907.32) 3871.73,3907.32 3990.79,3788.27 v1@4011.38,3788.27 ; v1@2854.36,3900.36 cw(c2871.16,3883.56) 2871.16,3907.32 cw(c2871.16,3931.08) v1@2854.36,3914.28 ; U1.24@3937.82,3521.99 ccw(c3927.41,3532.4) 3942.12,3532.4 ; U1.24@3942.13,3489.68 3942.13,3614.92 3958.11,3630.91 v1@4016.38,3630.91 ; 3942.13,3532.4 ccw(c3956.84,3532.4) U1.24@3946.44,3521.99 ; 3961.38,3817.67 ccw(c4005.94,3862.23) v1@4005.94,3799.21 ; 3981.55,3797.51 ccw(c4005.94,3821.9) v1@4005.94,3787.4 ; 3985.58,3630.9 cw(c3985.58,3605.93) v1@4003.24,3623.59 ; 3987.29,3630.9 ccw(c3987.29,3653.46) v1@4003.24,3637.51
  other v1: 4005.94,3789.37
GRID5: 5A.2 5B.2 5C.2 5D.2 5E.2 5F.2 5G.2 5H1.2 5H.2 U1.26 | length 5015.4
  Top Layer w11.81: 5E.2@2795.71,2625.83 2828.11,2625.83 ; 5F.2@2795.83,2777.52 2826.06,2777.52 ; 5E.2@2802.67,2618.87 cw(c2819.47,2602.06) 2819.47,2625.82 ; 5E.2@2802.67,2632.79 ccw(c2819.47,2649.59) 2819.47,2625.83 ; 5F.2@2802.79,2770.56 cw(c2819.59,2753.76) 2819.59,2777.52 cw(c2819.59,2801.28) 5F.2@2802.79,2784.48 ; 2832.28,2702.01 5G.2@2866.46,2702.01 ; 5A.2@2859.34,2838.47 ccw(c2842.54,2821.67) 2842.54,2845.43 ccw(c2842.54,2869.2) 5A.2@2859.34,2852.39 ; 5G.2@2859.5,2695.05 ccw(c2842.69,2678.25) 2842.69,2702.01 ccw(c2842.69,2725.77) 5G.2@2859.5,2708.97 ; 5D.2@2859.81,2550.87 ccw(c2843.01,2534.07) 2843.01,2557.83 ccw(c2843.01,2581.6) 5D.2@2859.81,2564.79 ; 5A.2@2873.26,2838.47 cw(c2890.06,2821.67) 2890.06,2845.43 cw(c2890.06,2869.2) 5A.2@2873.26,2852.39 ; 5D.2@2873.73,2550.87 cw(c2890.53,2534.07) 2890.53,2557.83 cw(c2890.53,2581.6) 5D.2@2873.73,2564.79 ; v1@2880.24,3950.83 cw(c2858.88,3929.47) 2889.09,3929.47 ; 2889.09,3938.59 cw(c2906.4,3938.59) v1@2894.16,3950.84 ; v1@2889.09,3951.38 2889.09,3571.06 2843.19,3525.16 2843.19,2967.8 2830.75,2955.35 2830.75,2835.98 ; 5C.2@2930.48,2619.1 cw(c2913.68,2602.3) 2937.44,2602.3 cw(c2961.2,2602.3) 5C.2@2944.4,2619.1 ; 5B.2@2930.48,2770.32 ccw(c2913.68,2753.52) 2913.68,2777.28 ccw(c2913.68,2801.05) 5B.2@2930.48,2784.24 ; 5C.2@2937.44,2626.06 2937.44,2575.16 2920.12,2557.83 5D.2@2866.77,2557.83 2838.07,2557.83 2830.75,2565.16 2830.75,2835.98 ; 5B.2@2937.44,2777.28 2908.78,2777.28 2900.59,2785.47 2900.59,2839.61 2894.76,2845.43 5A.2@2866.3,2845.43 2840.2,2845.43 2830.75,2835.98 ; v1@4396.94,3616.74 cw(c4368.27,3588.07) 4408.81,3588.07 ; v1@4396.94,3630.66 ccw(c4368.27,3659.33) 4408.81,3659.33 ; 5H.2@4401.85,3707.28 cw(c4385.05,3690.48) 4408.81,3690.48 cw(c4432.57,3690.48) 5H.2@4415.77,3707.28 ; 5H.2@4408.81,3724.09 ccw(c4408.81,3747.85) 4425.61,3731.05 ccw(c4442.42,3714.24) 5H.2@4418.65,3714.24 ; v1@4423.16,3781.66 cw(c4406.36,3764.86) 4430.12,3764.86 cw(c4453.88,3764.86) v1@4437.08,3781.66 ; v1(4430.12,3788.62) 4430.12,3735.55 5H.2@4408.81,3714.24 4408.81,3576.54 4412.77,3572.59 5H1.2@4554.21,3572.58 ; 5H1.2@4547.25,3565.62 ccw(c4530.44,3548.82) 4530.44,3572.58 ccw(c4530.44,3596.35) 5H1.2@4547.25,3579.55
  Bottom Layer w11.81: v1(2887.2,3957.8) 3908.23,3957.8 4077.95,3788.07 v1@4433.35,3788.07 ; v1@2894.16,3950.83 cw(c2910.97,3934.03) 2910.97,3957.79 cw(c2910.97,3981.56) v1@2894.16,3964.76 ; U1.26@4037.82,3521.99 ccw(c4027.41,3532.4) 4042.12,3532.4 ; U1.26@4042.13,3489.68 4042.13,3589.01 4076.61,3623.5 v1@4392.68,3623.5 ; 4042.13,3532.4 ccw(c4056.84,3532.4) U1.26@4046.44,3521.99 ; 4379.66,3623.5 ccw(c4379.66,3647.94) v1@4396.94,3630.66 ; 4380.61,3623.5 cw(c4380.61,3600.41) v1@4396.94,3616.74 ; 4405.02,3788.07 ccw(c4405.02,3813.71) v1@4423.16,3795.58 ; 4407.69,3788.07 cw(c4407.69,3766.19) v1@4423.16,3781.66
  other v1: 4403.9,3623.7
GRID6: 6A.2 6B.2 6C.2 6D.2 6E.2 6F.2 6G.2 6H1.2 6H.2 U1.28 | length 2495.9
  Top Layer w11.81: 6F.2@4588.66,2777.2 4624.13,2777.2 ; 6E.2@4588.74,2625.83 4624.53,2625.83 ; 6F.2@4595.62,2770.24 cw(c4612.42,2753.44) 4612.42,2777.2 cw(c4612.42,2800.97) 6F.2@4595.62,2784.16 ; 6E.2@4595.7,2618.87 cw(c4612.5,2602.06) 4612.5,2625.82 ; 6E.2@4595.7,2632.79 ccw(c4612.5,2649.59) 4612.5,2625.83 ; v1@4599.02,3416.11 cw(c4582.22,3399.31) 4605.98,3399.31 cw(c4629.75,3399.31) v1@4612.94,3416.11 ; v1(4605.98,3423.07) 4605.98,3361.1 4616.21,3350.88 6H.2@4687.58,3350.88 4687.58,3258.61 4671.06,3242.09 4671.06,3034.17 4692.09,3013.15 4692.09,2779.8 4694.65,2777.24 6B.2@4730.43,2777.24 ; 4625.79,2701.42 6G.2@4659.57,2701.42 ; 6D.2@4652.49,2551.07 ccw(c4635.69,2534.27) 4635.69,2558.03 ccw(c4635.69,2581.79) 6D.2@4652.49,2564.99 ; 6G.2@4652.61,2694.46 ccw(c4635.8,2677.66) 4635.8,2701.42 ccw(c4635.8,2725.18) 6G.2@4652.61,2708.38 ; 6A.2@4652.68,2838.67 ccw(c4635.88,2821.87) 4635.88,2845.63 ccw(c4635.88,2869.39) 6A.2@4652.68,2852.59 ; 4663.82,3350.87 cw(c4663.82,3327.11) 4680.62,3343.91 cw(c4663.82,3327.11) 4687.58,3327.11 cw(c4711.35,3327.11) 6H.2@4694.54,3343.91 ; 4663.82,3350.88 ccw(c4663.82,3374.64) 6H.2@4680.62,3357.84 ; 6D.2@4666.41,2551.07 cw(c4683.21,2534.27) 4683.21,2558.03 cw(c4683.21,2581.79) 6D.2@4666.41,2564.99 ; 6A.2@4666.61,2838.67 cw(c4683.41,2821.87) 4683.41,2845.63 cw(c4683.41,2869.39) 6A.2@4666.61,2852.59 ; 4671.38,3150.55 6H1.2@4738.45,3150.55 ; 4686.81,2845.63 6A.2@4659.65,2845.63 4631.57,2845.63 4624.57,2838.62 4624.57,2560.08 4626.61,2558.03 6D.2@4659.45,2558.03 4722.48,2558.03 4730.35,2565.91 6C.2@4730.35,2625.91 ; 6C.2@4723.39,2618.94 cw(c4706.59,2602.14) 4730.35,2602.14 cw(c4754.12,2602.14) 6C.2@4737.31,2618.94 ; 6B.2@4723.47,2770.28 ccw(c4706.67,2753.48) 4706.67,2777.24 ccw(c4706.67,2801.01) 6B.2@4723.47,2784.2 ; 6H1.2@4731.49,3143.59 ccw(c4714.69,3126.79) 4714.69,3150.55 ccw(c4714.69,3174.31) 6H1.2@4731.49,3157.51
  Bottom Layer w11.81: U1.28@4142.13,3489.68 4261.18,3489.68 4324.57,3426.3 v1@4606.57,3426.3 ; U1.28@4146.44,3485.37 cw(c4156.84,3474.97) 4156.84,3489.68 cw(c4156.84,3504.4) U1.28@4146.44,3493.99 ; 4574.43,3426.3 cw(c4574.43,3391.51) v1@4599.02,3416.11 ; 4590.02,3426.3 ccw(c4590.02,3439.04) v1@4599.02,3430.03
GRID7: 7A.2 7B.2 7C.2 7D.2 7E.2 7F.2 7G.2 7H1.2 7H.2 U1.2 | length 3877.7
  Top Layer w11.81: 7H.2@3742.45,2264.56 ccw(c3725.65,2281.36) 3749.41,2281.36 ccw(c3773.17,2281.36) 7H.2@3756.37,2264.56 ; 7H.2@3749.41,2257.6 3749.41,2307.48 3760.47,2318.54 4193.58,2318.54 4318.5,2443.46 v1@4318.5,2619.41 ; 7H1.2@3951.31,2264.48 ccw(c3934.51,2281.28) 3958.27,2281.28 ccw(c3982.03,2281.28) 7H1.2@3965.23,2264.48 ; 7H1.2@3958.27,2257.52 3958.27,2318.54 ; v1@4312.76,2611.58 cw(c4298.91,2597.73) 4318.5,2597.73 ; 4318.5,2591.83 cw(c4346.43,2591.83) v1@4326.68,2611.58 ; v1@4443.08,3177.09 cw(c4426.28,3160.29) 4450.04,3160.29 cw(c4473.8,3160.29) v1@4457,3177.09 ; v1@4444.1,2630.31 ccw(c4429.77,2644.64) 4450.04,2644.64 ; v1@4450.04,2632.09 v1(4450.04,3184.05) ; 4450.04,2649.58 ccw(c4477.3,2649.58) v1@4458.02,2630.31 ; 7E.2@4801.34,2625.63 4837.24,2625.63 ; 7F.2@4801.34,2777.32 4837.95,2777.32 ; 7E.2@4808.3,2618.67 cw(c4825.1,2601.87) 4825.1,2625.63 cw(c4825.1,2649.39) 7E.2@4808.3,2632.59 ; 7F.2@4808.3,2770.36 cw(c4825.1,2753.56) 4825.1,2777.32 cw(c4825.1,2801.08) 7F.2@4808.3,2784.28 ; v1@4826.66,2570.42 ccw(c4798.55,2598.54) 4838.31,2598.54 ; v1@4840.58,2570.42 ccw(c4870.69,2600.53) 7D.2@4870.69,2557.95 ; 4840.94,2701.61 7G.2@4872.12,2701.61 4908.66,2701.61 ; 7A.2@4864.9,2838.42 ccw(c4848.94,2823.12) 4848.94,2845.24 ; 7A.2@4864.9,2852.05 cw(c4848.94,2867.35) 4848.94,2845.24 ; 7G.2@4865.17,2694.65 ccw(c4848.36,2677.85) 4848.36,2701.61 ccw(c4848.36,2725.38) 7G.2@4865.17,2708.57 ; 7D.2@4865.28,2550.99 ccw(c4848.48,2534.19) 4848.48,2557.95 ccw(c4848.48,2581.71) 7D.2@4865.28,2564.91 ; 7A.2@4872.01,2845.24 4848.94,2845.24 ; 7D.2@4872.24,2557.95 4844.8,2557.95 4838.31,2564.45 4838.31,2834.61 4848.94,2845.24 ; 7G.2@4879.09,2694.65 cw(c4895.89,2677.85) 4895.89,2701.61 cw(c4895.89,2725.38) 7G.2@4879.09,2708.57 ; 7C.2@4935.83,2618.63 ccw(c4919.03,2601.83) 4919.03,2625.59 ccw(c4919.03,2649.35) 7C.2@4935.83,2632.55 ; 7B.2@4936.15,2770.2 ccw(c4919.35,2753.4) 4919.35,2777.16 ccw(c4919.35,2800.93) 7B.2@4936.15,2784.13 ; 7C.2@4942.8,2625.59 4914.76,2625.59 4909.61,2630.75 4909.61,2774.37 4912.4,2777.16 7B.2@4943.11,2777.16
  Bottom Layer w11.81: U1.2@4087.82,3141.99 ccw(c4077.41,3152.4) 4092.12,3152.4 ; U1.2@4092.13,3109.68 4092.13,3174.61 4103.31,3185.79 v1@4454.02,3185.79 ; 4092.13,3152.4 ccw(c4106.84,3152.4) U1.2@4096.44,3141.99 ; v1@4324.53,2623.35 v1(4451.06,2623.35) 4683.54,2623.35 4741.97,2564.92 v1@4831.42,2564.92 ; v1@4326.68,2611.58 cw(c4355.08,2583.18) 4355.08,2623.34 ; 4422.1,3185.79 cw(c4422.1,3156.11) v1@4443.08,3177.1 ; 4430.46,3185.79 ccw(c4430.46,3203.63) v1@4443.08,3191.01 ; v1@4444.1,2616.39 ccw(c4427.3,2599.58) 4427.3,2623.34 ccw(c4427.3,2647.11) v1@4444.1,2630.31 ; v1@4458.02,2616.39 cw(c4474.82,2599.58) 4474.82,2623.34 cw(c4474.82,2647.11) v1@4458.02,2630.31 ; 4806.34,2564.92 cw(c4806.34,2536.18) v1@4826.66,2556.5 ; 4813.38,2564.92 ccw(c4813.38,2583.71) v1@4826.66,2570.42
  other v1: 4833.62,2563.46 4319.72,2618.54
GRID8: 8A.2 8B.2 8C.2 8D.2 8E.2 8F.2 8G.2 8H.2 U1.4 | length 4617.4
  Top Layer w11.81: 8H.2@3393,2264.56 ccw(c3376.2,2281.36) 3399.96,2281.36 ccw(c3423.72,2281.36) 8H.2@3406.92,2264.56 ; 8H.2@3399.96,2257.6 3399.96,2317.32 3449.33,2366.69 v1(4110.83,2366.69) ; v1@4103.87,2359.73 ccw(c4087.06,2342.93) 4087.06,2366.69 ccw(c4087.06,2390.45) v1@4103.87,2373.65 ; v1@4399.69,3212.29 cw(c4382.89,3195.49) 4406.65,3195.49 cw(c4430.41,3195.49) v1@4413.61,3212.29 ; v1@4400.76,2516.72 ccw(c4386.52,2530.96) 4406.65,2530.96 ; v1@4406.65,2505.24 v1(4406.65,3219.25) ; 4406.65,2536.09 ccw(c4434.04,2536.09) v1@4414.68,2516.72 ; 4990.02,2625.82 cw(c4990.02,2602.06) 5006.82,2618.87 cw(c4990.02,2602.06) 5013.78,2602.06 cw(c5037.54,2602.06) 8E.2@5020.74,2618.87 ; 4990.02,2625.83 ccw(c4990.02,2649.59) 8E.2@5006.82,2632.79 ; 8F.2@5006.94,2770.56 ccw(c4990.14,2753.76) 4990.14,2777.52 ccw(c4990.14,2801.28) 8F.2@5006.94,2784.48 ; 5013.78,2595.41 ccw(c5056.63,2595.41) 5026.33,2565.11 ccw(c5043.42,2582.2) 5043.42,2558.03 ; 8F.2@5013.9,2777.52 4986.73,2777.52 4978.54,2769.33 4978.54,2631.38 4984.09,2625.83 8E.2@5013.78,2625.83 5013.78,2565.47 5021.22,2558.03 8D.2@5084.68,2558.03 5112.91,2558.03 5119.65,2564.76 5119.65,2834.88 5109.29,2845.24 8A.2@5084.96,2845.24 ; v1@5026.33,2551.19 cw(c5042.85,2534.67) 5042.85,2558.03 ; 8D.2@5077.72,2551.07 ccw(c5060.92,2534.27) 5060.92,2558.03 ccw(c5060.92,2581.79) 8D.2@5077.72,2564.99 ; 8G.2@5084.68,2701.42 5117.83,2701.42 ; 8D.2@5091.64,2551.07 cw(c5108.45,2534.27) 5108.45,2558.03 cw(c5108.45,2581.79) 8D.2@5091.64,2564.99 ; 8G.2@5091.64,2694.46 cw(c5108.45,2677.66) 5108.45,2701.42 cw(c5108.45,2725.18) 8G.2@5091.64,2708.38 ; 8A.2@5091.92,2838.28 cw(c5108.72,2821.47) 5108.72,2845.24 cw(c5108.72,2869) 8A.2@5091.92,2852.2 ; 5120.04,2777.28 8B.2@5155.71,2777.28 ; 5120.43,2625.91 8C.2@5155.39,2625.91 5129.8,2625.91 ; 8B.2@5148.75,2770.32 ccw(c5131.95,2753.52) 5131.95,2777.28 ccw(c5131.95,2801.05) 8B.2@5148.75,2784.24 ; 5131.63,2625.9 cw(c5131.63,2602.14) 5148.43,2618.94 ccw(c5131.63,2602.14) 5131.63,2625.9 ; 5131.63,2625.91 ccw(c5131.63,2649.67) 5148.43,2632.87 cw(c5131.63,2649.67) 5131.63,2625.91
  Bottom Layer w11.81: U1.4@3987.82,3141.99 ccw(c3977.41,3152.4) 3992.12,3152.4 ; U1.4@3992.13,3109.68 3992.13,3181.1 4022.83,3211.81 v1@4402.32,3211.81 ; 3992.13,3152.4 ccw(c4006.84,3152.4) U1.4@3996.44,3141.99 ; v1@4115.98,2365.98 4263.94,2365.98 v1(4407.72,2509.76) 4972.52,2509.76 v1@5023.86,2561.1 ; v1@4117.79,2359.73 cw(c4132.88,2344.64) 4132.88,2365.98 ; v1@4117.79,2373.65 ccw(c4136.3,2392.16) 4136.3,2365.98 ; 4364.93,3211.81 ccw(c4364.93,3260.98) v1@4399.69,3226.21 ; v1@4397.87,2509.76 cw(c4374.11,2509.76) 4390.91,2492.96 cw(c4407.72,2476.16) v1@4407.72,2499.92 ; v1@4414.68,2502.8 cw(c4431.48,2486) 4431.48,2509.76 cw(c4431.48,2533.53) v1@4414.68,2516.72 ; 5001.48,2538.73 ccw(c4982.06,2558.15) v1@5009.53,2558.15 ; 5005.19,2542.43 cw(c5019.37,2528.25) v1@5019.37,2548.31
  other v1: 5019.37,2558.15
Net9A_1: 9A.1 RS1.1 | length 371.2
  Top Layer w11.81: 9A.1@2626.69,3702.91 v1@2767.56,3702.91 ; 9A.1@2633.65,3695.95 cw(c2650.45,3679.15) 2650.45,3702.91 cw(c2650.45,3726.68) 9A.1@2633.65,3709.87 ; 2733.12,3702.91 ccw(c2733.12,3730.98) v1@2752.96,3711.13 ; 2739.2,3702.91 cw(c2739.2,3683.45) v1@2752.96,3697.21
  Bottom Layer w11.81: v1@2752.96,3697.21 cw(c2723.9,3668.15) 2765,3668.15 ; RS1.1@2758.04,3619.95 ccw(c2741.24,3636.75) 2765,3636.75 ccw(c2788.76,3636.75) RS1.1@2771.96,3619.95 ; RS1.1@2765,3612.99 v1@2765,3699.09
  other v1: 2759.92,3704.17
Net9B_1: 9B.1 RS2.1 | length 275.8
  Top Layer w11.81: v1@3794.76,2953.23 9B.1@3840.59,2953.23 ; v1@3805.19,2946.23 cw(c3822.09,2929.33) 3822.09,2953.23 ; v1@3805.19,2960.15 ccw(c3821.89,2976.86) 3821.89,2953.23 ; 9B.1@3833.63,2946.27 ccw(c3816.83,2929.47) 3816.83,2953.23 ccw(c3816.83,2976.99) 9B.1@3833.63,2960.19
  Bottom Layer w11.81: RS2.1@3705.24,2949.41 v1@3794.45,2949.41 ; RS2.1@3712.2,2942.45 cw(c3729,2925.65) 3729,2949.41 cw(c3729,2973.17) RS2.1@3712.2,2956.37 ; 3765.34,2949.41 ccw(c3765.34,2986.07) v1@3791.27,2960.15
  other v1: 3798.23,2953.19
Net9C_1: 9C.1 RS3.1 | length 474.5
  Top Layer w11.81: 9C.1@3061.62,2673.69 ccw(c3044.82,2690.49) 3068.58,2690.49 ccw(c3092.34,2690.49) 9C.1@3075.54,2673.69 ; v1@3062.61,2876.07 cw(c3048.18,2861.65) 3068.58,2861.65 ; 9C.1@3068.58,2666.73 v1@3068.58,2877.4 ; 3068.58,2856.89 cw(c3095.7,2856.89) v1@3076.53,2876.07
  Bottom Layer w11.81: v1@3071.81,2885.28 RS3.1@3186.34,2885.28 ; v1@3076.53,2876.07 cw(c3098.75,2853.85) 3098.75,2885.27 ; v1@3076.53,2889.99 ccw(c3087.91,2901.38) 3087.91,2885.28 ; 3162.58,2885.27 cw(c3162.58,2861.51) RS3.1@3179.38,2878.31 ; 3162.58,2885.28 ccw(c3162.58,2909.04) RS3.1@3179.38,2892.24
  other v1: 3069.57,2883.03
Net9D_1: 9D.1 RS4.1 | length 320.4
  Top Layer w11.81: v1@4969.76,3687.13 9D.1@5073.74,3687.13 ; v1@4976.6,3679.42 cw(c4995.21,3660.81) 4995.21,3687.12 ; v1@4976.61,3693.34 ccw(c4991.6,3708.33) 4991.6,3687.13 ; 5049.98,3687.12 cw(c5049.98,3663.36) 9D.1@5066.78,3680.17 ; 5049.98,3687.13 ccw(c5049.98,3710.89) 9D.1@5066.78,3694.09
  Bottom Layer w11.81: RS4.1@4891.26,3690.79 v1@4965.24,3690.79 ; RS4.1@4898.22,3683.83 cw(c4915.02,3667.03) 4915.02,3690.79 cw(c4915.02,3714.55) RS4.1@4898.22,3697.75 ; 4935.24,3690.79 cw(c4935.24,3651.97) v1@4962.69,3679.42
  other v1: 4969.65,3686.38
Net9E_1: 9E.1 RS5.1 | length 391.2
  Top Layer w11.81: v1@5225.72,2526.88 ccw(c5203.21,2549.39) 5235.04,2549.39 ; v1@5235.04,2521.34 5235.04,2654.8 5247.4,2667.16 9E.1@5278.46,2667.16 ; 5235.04,2537.98 ccw(c5250.74,2537.98) v1@5239.64,2526.88 ; 9E.1@5271.5,2660.2 ccw(c5254.7,2643.4) 5254.7,2667.16 ccw(c5254.7,2690.93) 9E.1@5271.5,2674.13
  Bottom Layer w11.81: v1@5232.68,2510.08 cw(c5232.68,2486.32) 5249.48,2503.12 cw(c5266.28,2519.92) v1@5242.52,2519.92 ; v1(5232.68,2519.92) 5250.55,2502.05 RS5.1@5250.55,2467.4 ; RS5.1@5243.59,2474.36 ccw(c5226.79,2491.16) 5250.55,2491.16 ccw(c5274.31,2491.16) RS5.1@5257.51,2474.36
NetC6_1: C6.1 D2.2 L1.1 U2.1 | length 788.8
  Bottom Layer w11.81: C6.1@4705.43,3113.62 4707.64,3113.62 D2.2@4775.39,3181.38 ; C6.1@4705.43,3123.46 ccw(c4705.43,3152.55) 4726,3131.98 ; C6.1@4715.28,3113.62 cw(c4733.72,3113.62) C6.1@4720.68,3126.66 ; 4748.11,3154.1 cw(c4780.71,3121.5) D2.2@4780.71,3167.6 ; L1.1@4757.89,3260.92 cw(c4702.8,3205.83) 4780.71,3205.83 ; L1.1@4766.24,3269.27 cw(c4731.31,3234.34) 4780.71,3234.34 ; D2.2@4773.75,3192.27 ccw(c4756.95,3209.08) 4780.71,3209.08 ccw(c4804.47,3209.08) D2.2@4787.67,3192.27 ; L1.1@4775.98,3328.23 4828.78,3328.23 ; D2.2@4780.71,3181.38 L1.1@4780.71,3323.5 ; 4780.71,3228.64 cw(c4826.36,3228.64) L1.1@4794.08,3260.92 ; L1.1@4796.07,3312.37 cw(c4828.78,3286.57) 4828.78,3328.23 ; L1.1@4796.07,3344.08 ccw(c4828.78,3369.89) 4828.78,3328.23 ; 4868.47,3288.54 ccw(c4907.52,3327.58) U2.1@4907.52,3272.36 ; 4888.63,3268.37 ccw(c4907.52,3287.26) U2.1@4907.52,3260.55 ; U2.1@4907.52,3253.66 4903.35,3253.66 4828.78,3328.23
NetC6_2: C6.2 U2.8 | length 249.8
  Bottom Layer w11.81: C6.2@4768.43,3113.62 4893.86,3113.62 4907.52,3099.96 U2.8@4907.52,3050.91 ; C6.2@4775.39,3106.66 cw(c4792.19,3089.86) 4792.19,3113.62 cw(c4792.19,3137.38) C6.2@4775.39,3120.58 ; U2.8@4904.04,3068.16 ccw(c4895.64,3076.57) 4907.52,3076.57 ccw(c4919.4,3076.57) U2.8@4911,3068.16
NetC7_1: C7.1 R6.2 | length 162.8
  Bottom Layer w11.81: R6.2@5168.7,3301.73 cw(c5168.7,3277.97) 5185.5,3294.77 cw(c5202.31,3311.57) R6.2@5178.54,3311.57 ; R6.2@5170.31,3311.57 R6.2@5168.7,3311.57 5228.78,3251.5 C7.1@5230.39,3251.5 ; 5210.84,3269.44 ccw(c5230.39,3289) C7.1@5230.39,3261.34 ; C7.1@5214.73,3265.54 cw(c5200.69,3251.5) C7.1@5220.55,3251.5
NetC7_2: C7.2 U2.3 | length 288.5
  Bottom Layer w11.81: U2.3@5004.04,3270.92 ccw(c4995.64,3279.32) 5007.52,3279.32 ccw(c5019.4,3279.32) U2.3@5011,3270.92 ; U2.3@5007.52,3253.66 5007.52,3298.15 5018.11,3308.74 5076.81,3308.74 5134.06,3251.5 C7.2@5167.4,3251.5 ; C7.2@5160.44,3244.54 ccw(c5143.64,3227.73) 5143.64,3251.49 ccw(c5143.64,3275.26) C7.2@5160.44,3258.46
NetR3_1: R3.1 R4.2 U2.2 | length 947.7
  Top Layer w11.81: v1@4855.76,3062.51 ccw(c4833.06,3085.21) 4865.16,3085.21 ; v1@4858.2,3194.46 cw(c4841.4,3177.66) 4865.16,3177.66 cw(c4888.92,3177.66) v1@4872.12,3194.46 ; v1@4865.16,3052.76 v1(4865.16,3201.42) ; 4865.16,3073.42 ccw(c4880.59,3073.42) v1@4869.68,3062.51
  Bottom Layer w11.81: R4.2@4766.73,3052.76 v1@4859.92,3052.76 ; R4.2@4773.69,3045.8 cw(c4790.49,3028.99) 4790.49,3052.76 cw(c4790.49,3076.52) R4.2@4773.69,3059.72 ; 4813.66,2935.24 R3.1@4768.23,2935.24 4826.42,2935.24 4862.72,2971.53 v1(4862.72,3055.55) ; 4832.21,3052.76 ccw(c4832.21,3086.06) v1@4855.76,3062.51 ; 4845.7,3052.75 cw(c4845.7,3038.54) 4855.76,3048.59 cw(c4838.95,3031.79) 4862.72,3031.79 cw(c4886.48,3031.79) v1@4869.68,3048.59 ; v1@4856.77,3200.32 4949.8,3200.32 4957.52,3208.03 U2.2@4957.52,3253.66 ; v1@4872.12,3194.46 cw(c4886.26,3180.32) 4886.26,3200.31 ; v1@4872.12,3208.38 ccw(c4891.58,3227.84) 4891.58,3200.32 ; U2.2@4954.04,3236.4 cw(c4945.64,3228) 4957.52,3228 cw(c4969.4,3228) U2.2@4961,3236.4 ; 4791.99,2935.24 cw(c4791.99,2959) 4775.19,2942.2 ccw(c4791.99,2959) 4791.99,2935.24 ; 4791.99,2935.24 ccw(c4791.99,2911.47) 4775.19,2928.28 cw(c4791.99,2911.47) 4791.99,2935.24
NetR5_2: R5.2 U2.6 | length 284.3
  Bottom Layer w11.81: U2.6@5004.04,3068.16 ccw(c4995.64,3076.57) 5007.52,3076.57 ccw(c5019.4,3076.57) U2.6@5011,3068.16 ; U2.6@5007.52,3050.91 5007.52,3101.46 5020.24,3114.17 5077.05,3114.17 5116.93,3074.29 R5.2@5163.54,3074.29 ; R5.2@5156.58,3067.33 ccw(c5139.78,3050.53) 5139.78,3074.29 ccw(c5139.78,3098.05) R5.2@5156.58,3081.25
NetR7_1: R7.1 R8.2 U2.4 | length 348.8
  Bottom Layer w11.81: U2.4@5054.04,3236.4 cw(c5045.64,3228) 5057.52,3228 cw(c5069.4,3228) U2.4@5061,3236.4 ; U2.4@5057.52,3253.66 5057.52,3210.63 5076.3,3191.85 R8.2@5166.1,3191.85 R7.1@5166.1,3133.07 ; R7.1@5159.14,3140.03 ccw(c5142.34,3156.83) 5166.1,3156.83 ccw(c5189.86,3156.83) R7.1@5173.06,3140.03 ; R8.2@5159.14,3198.81 cw(c5142.34,3215.61) 5142.34,3191.85 cw(c5142.34,3168.09) 5159.14,3184.89 cw(c5142.34,3168.09) 5166.1,3168.09 cw(c5189.86,3168.09) R8.2@5173.06,3184.89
